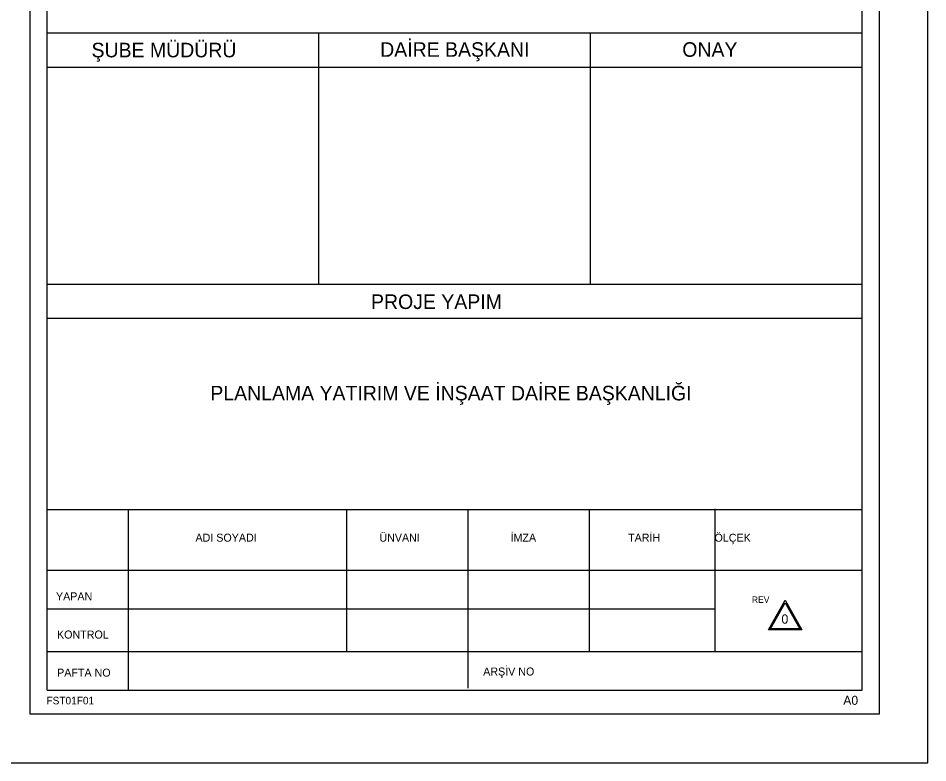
# Model space of a CAD drawing. Extents: x 314 to 1145, y -10 to 574.
# Drawn here: x 957.5 to 1145, y -10 to 143.5 of the extents above; entities that cross this region are included whole.
import ezdxf

# ---------------------------------------------------------------- set-up
doc = ezdxf.new("R2010")
doc.units = 0
for name, color, linetype in [('Level 1', 7, 'Continuous'), ('Level 51', 7, 'Continuous'), ('Level 6', 7, 'Continuous'), ('Level 7', 7, 'Continuous')]:
    doc.layers.add(name, color=color, linetype=linetype)

msp = doc.modelspace()

# ---------------------------------------------------------------- linework, layer by layer
at = {"layer": 'Level 1'}
for p, q in [((960, 0), (960, 287)), ((1135, 287), (1135, 0)), ((1135, 0), (960, 0))]:
    msp.add_line(p, q, dxfattribs=at)
at = {"layer": 'Level 51'}
msp.add_lwpolyline([(314, -10), (1145, -10), (1145, 574), (314, 574)], close=True, dxfattribs=at)
at = {"layer": 'Level 6'}
for p, q in [((963.47, 4.97), (963.47, 267.9)), ((1131.45, 4.97), (1131.45, 267.9)), ((1131.45, 4.97), (1131.45, 267.9)), ((1131.45, 4.97), (1131.45, 267.9)), ((1131.45, 4.97), (1131.45, 267.9)), ((963.47, 140.48), (1131.45, 140.48)), ((963.47, 140.48), (1131.45, 140.48)), ((963.47, 140.48), (1131.45, 140.48)), ((963.47, 140.48), (1131.45, 140.48)), ((1019.47, 88.65), (1019.47, 140.48)), ((1075.47, 88.65), (1075.47, 140.48)), ((963.47, 133.4), (1131.45, 133.4)), ((963.47, 133.4), (1131.45, 133.4)), ((963.47, 133.4), (1131.45, 133.4)), ((963.47, 88.65), (1131.45, 88.65)), ((963.47, 88.65), (1131.45, 88.65)), ((963.47, 88.65), (1131.45, 88.65)), ((963.47, 88.65), (1131.45, 88.65)), ((963.47, 81.62), (1131.45, 81.62)), ((963.47, 42.24), (1131.45, 42.24)), ((963.47, 42.24), (1131.45, 42.24)), ((963.47, 42.24), (1131.45, 42.24)), ((963.47, 42.24), (1131.45, 42.24)), ((980.23, 4.97), (980.23, 42.1)), ((1025.23, 13.02), (1025.23, 42.1)), ((1050.23, 5.36), (1050.23, 42.1)), ((1075.23, 12.98), (1075.23, 42.1)), ((1101.07, 42.34), (1101.07, 13.04)), ((963.34, 29.74), (1131.31, 29.74)), ((963.47, 21.72), (1101.07, 21.72)), ((963.47, 12.95), (1131.32, 12.95)), ((963.47, 4.97), (1131.45, 4.97)), ((963.47, 4.97), (1131.45, 4.97)), ((963.47, 4.97), (1131.45, 4.97)), ((963.47, 4.97), (1131.45, 4.97))]:
    msp.add_line(p, q, dxfattribs=at)
at = {"layer": 'Level 7'}
for points in [[(1112.18, 17.38), (1115.59, 23.5), (1119.01, 17.38)], [(1112.18, 17.38), (1115.59, 23.5), (1119.01, 17.38)], [(1112.18, 17.38), (1115.59, 23.5), (1119.01, 17.38)], [(1112.18, 17.38), (1115.59, 23.5), (1119.01, 17.38)], [(1112.6, 17.63), (1115.59, 22.99), (1118.59, 17.63)], [(1112.6, 17.63), (1115.59, 22.99), (1118.59, 17.63)], [(1112.6, 17.63), (1115.59, 22.99), (1118.59, 17.63)], [(1112.6, 17.63), (1115.59, 22.99), (1118.59, 17.63)]]:
    msp.add_lwpolyline(points, close=True, dxfattribs=at)

# ---------------------------------------------------------------- texts
at = {"layer": 'Level 1'}
msp.add_text('0', height=1.92, dxfattribs=at).set_placement((1114.82, 18.67))
at = {"layer": 'Level 7'}
for s, height, p in [('ŞUBE MÜDÜRÜ', 3, (972.62, 135.41)), ('DAİRE BAŞKANI', 3, (1032.12, 135.52)), ('ONAY', 3, (1094.39, 135.52)), ('PROJE YAPIM', 3, (1030.23, 83.54)), ('PLANLAMA YATIRIM VE İNŞAAT DAİRE BAŞKANLIĞI', 3, (997.1, 64.7)), ('ÜNVANI', 1.65, (1031.95, 35.58)), ('İMZA', 1.65, (1058.99, 35.58)), ('TARİH', 1.65, (1083.22, 35.58)), ('ÖLÇEK', 1.65, (1101.03, 35.57)), ('ADI SOYADI', 1.65, (994.04, 35.58)), ('YAPAN', 1.65, (965.29, 23.48)), ('REV', 1.32, (1108.73, 22.97)), ('KONTROL', 1.65, (965.5, 15.61)), ('PAFTA NO', 1.65, (965.52, 7.76)), ('ARŞİV NO', 1.65, (1053.35, 7.99)), ('A0', 1.866, (1127.58, 1.95)), ('FST01F01', 1.555, (963.33, 2.05))]:
    msp.add_text(s, height=height, dxfattribs=at).set_placement(p)

doc.saveas('drawing.dxf')
